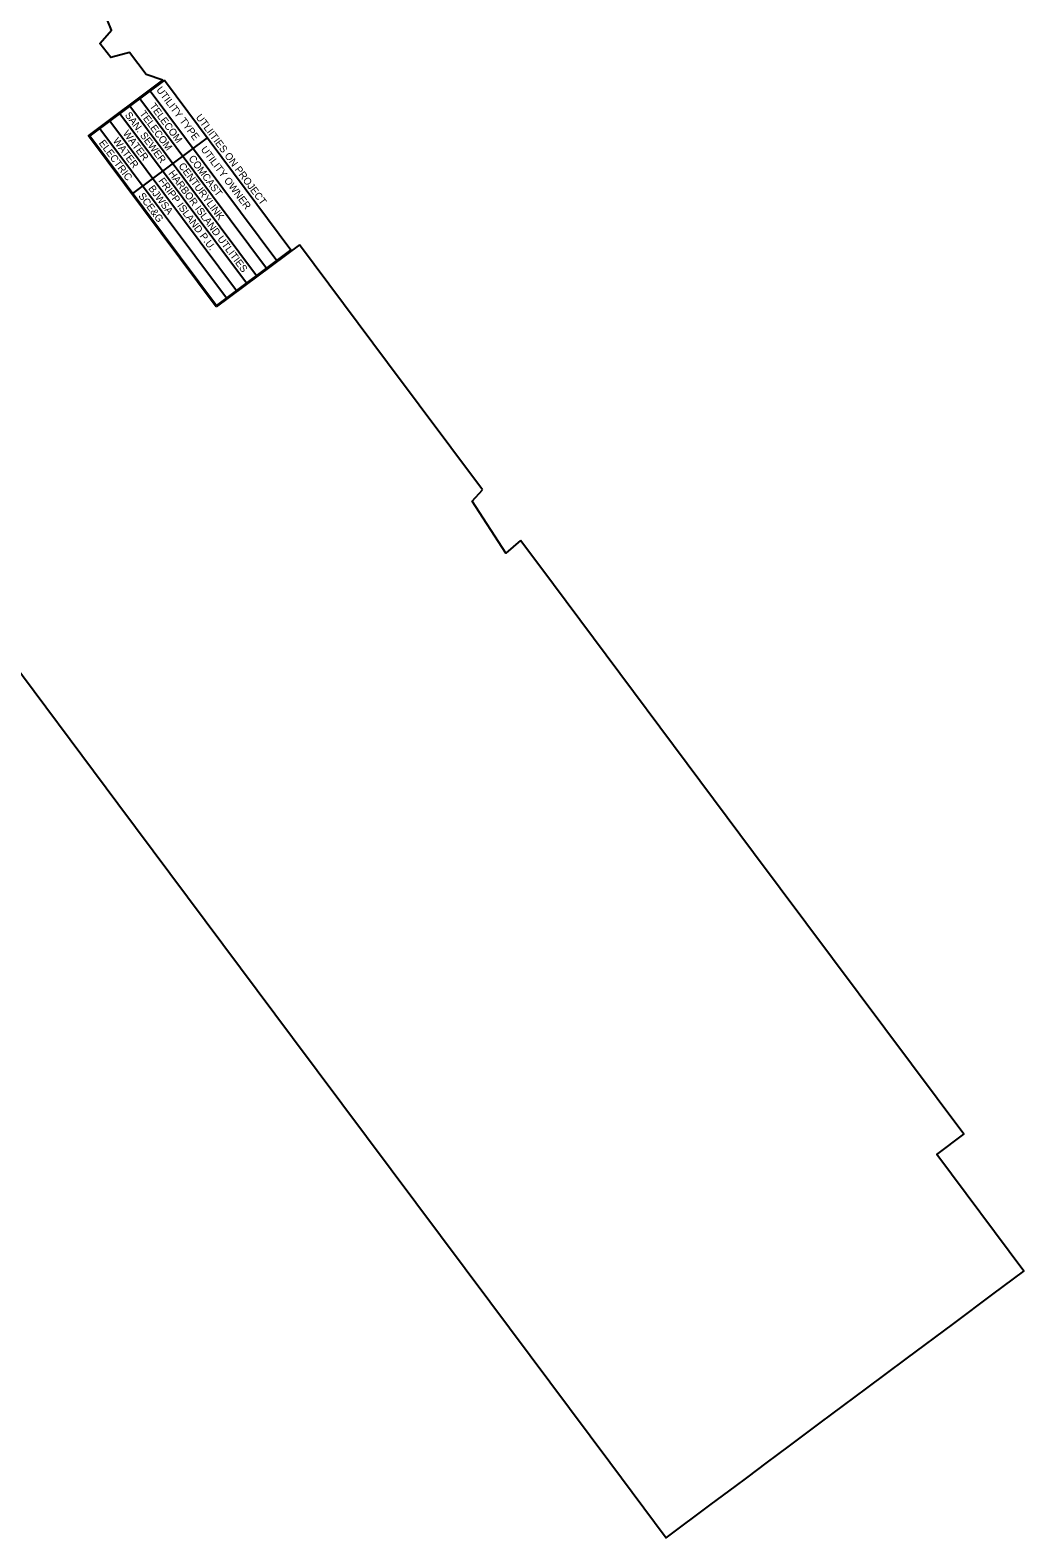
# Model space of a CAD drawing. Extents: x 2162629 to 2176228, y 202467 to 210920.
# Drawn here: x 2171185 to 2172214, y 205819 to 207382 of the extents above; entities that cross this region are included whole.
import ezdxf

# ---------------------------------------------------------------- set-up
doc = ezdxf.new("R2010")
doc.units = 0
doc.layers.add('RD_SHT_ShtClip', color=7, linetype='Continuous')
doc.layers.add('RD_SHT_TX', color=7, linetype='Continuous')

msp = doc.modelspace()

# ---------------------------------------------------------------- linework, layer by layer
at = {"layer": 'RD_SHT_ShtClip'}
msp.add_line((2171463.9, 207159.5), (2171377.6, 207095.1), dxfattribs=at)
for points in [[(2171322.5, 207330), (2171305.2, 207335.7), (2171288, 207358.6), (2171268.6, 207353.5), (2171257, 207368.1), (2171267, 207379.5), (2171269.1, 207381.9), (2171264.7, 207393), (2171256.9, 207404.5), (2171263.1, 207419.8), (2171266.9, 207423.4)], [(2171377.6, 207095.1), (2171245.3, 207272.4), (2171322.5, 207330)], [(2171653.5, 206905.5), (2171555.2, 207037.2), (2171463.9, 207159.5)], [(2171692.7, 206853), (2171677.7, 206840), (2171642.9, 206893.8), (2171653.5, 206905.5)], [(2171947.2, 205896.7), (2171971.6, 205914.8), (2172003.4, 205938.6), (2172051.6, 205974.6), (2172092.2, 206004.9), (2172141.6, 206041.7), (2172182.2, 206072.1), (2172214.2, 206095.9), (2172124, 206216.8), (2172152, 206237.8), (2171934.3, 206529.4), (2171712.7, 206826.2), (2171692.7, 206853)], [(2171151.5, 206746.8), (2171275.8, 206580.4), (2171456.7, 206338), (2171661, 206064.3), (2171785.3, 205897.8), (2171843.8, 205819.5), (2171890.3, 205854.2), (2171915.1, 205872.6)], [(2171915.1, 205872.6), (2171927.3, 205881.8), (2171938.5, 205890.2), (2171947.2, 205896.7)]]:
    msp.add_lwpolyline(points, dxfattribs=at)
at = {"layer": 'RD_SHT_TX'}
for p, q in [((2171324, 207329.9), (2171246.7, 207272.2)), ((2171324, 207329.9), (2171455.1, 207154.2)), ((2171298.7, 207311), (2171429.9, 207135.3)), ((2171309.2, 207318.8), (2171440.3, 207143.1)), ((2171277.9, 207295.5), (2171409.1, 207119.8)), ((2171288.3, 207303.3), (2171419.5, 207127.6)), ((2171257.1, 207279.9), (2171388.3, 207104.3)), ((2171267.5, 207287.7), (2171398.7, 207112)), ((2171246.7, 207272.2), (2171377.8, 207096.5)), ((2171368.4, 207270.4), (2171291.1, 207212.7)), ((2171455.1, 207154.2), (2171377.8, 207096.5))]:
    msp.add_line(p, q, dxfattribs=at)

# ---------------------------------------------------------------- texts
for s, p in [('UTILITY TYPE', (2171315.2, 207319.9)), ('SAN. SEWER', (2171282.7, 207293.7)), ('TELECOM', (2171297.8, 207295.1)), ('TELECOM', (2171308.2, 207302.9)), ('UTLIITIES ON PROJECT', (2171356.1, 207291.4)), ('WATER', (2171280.6, 207274.7)), ('ELECTRIC', (2171255.7, 207264.7)), ('WATER', (2171270.2, 207267)), ('COMCAST', (2171348.6, 207248.8)), ('UTILITY OWNER', (2171361.3, 207258.2)), ('HARBOR ISLAND UTLITIES', (2171327.8, 207233.2)), ('CENTURYLINK', (2171338.2, 207241)), ('BJWSA', (2171307, 207217.7)), ('FRIPP ISLAND P.U.', (2171317.4, 207225.5)), ('SCE&G', (2171296.6, 207209.9))]:
    msp.add_text(s, height=7.5, rotation=306.7411, dxfattribs=at).set_placement(p)

doc.saveas('drawing.dxf')
